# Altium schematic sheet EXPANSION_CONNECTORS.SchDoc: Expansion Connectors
size A3; Date: Not used; ApprovedBy: Not used; CheckedBy: Not used; Author: Not used; CompanyName: STMicroelectronics; DrawnBy: Not used; Engineer: Not used; Organization: Not used; Address1: Not used; Address2: Not used; Address3: Not used; Address4: Not used; DocumentNumber: Not used; Revision: Not used; SheetNumber: 13; SheetTotal: 16
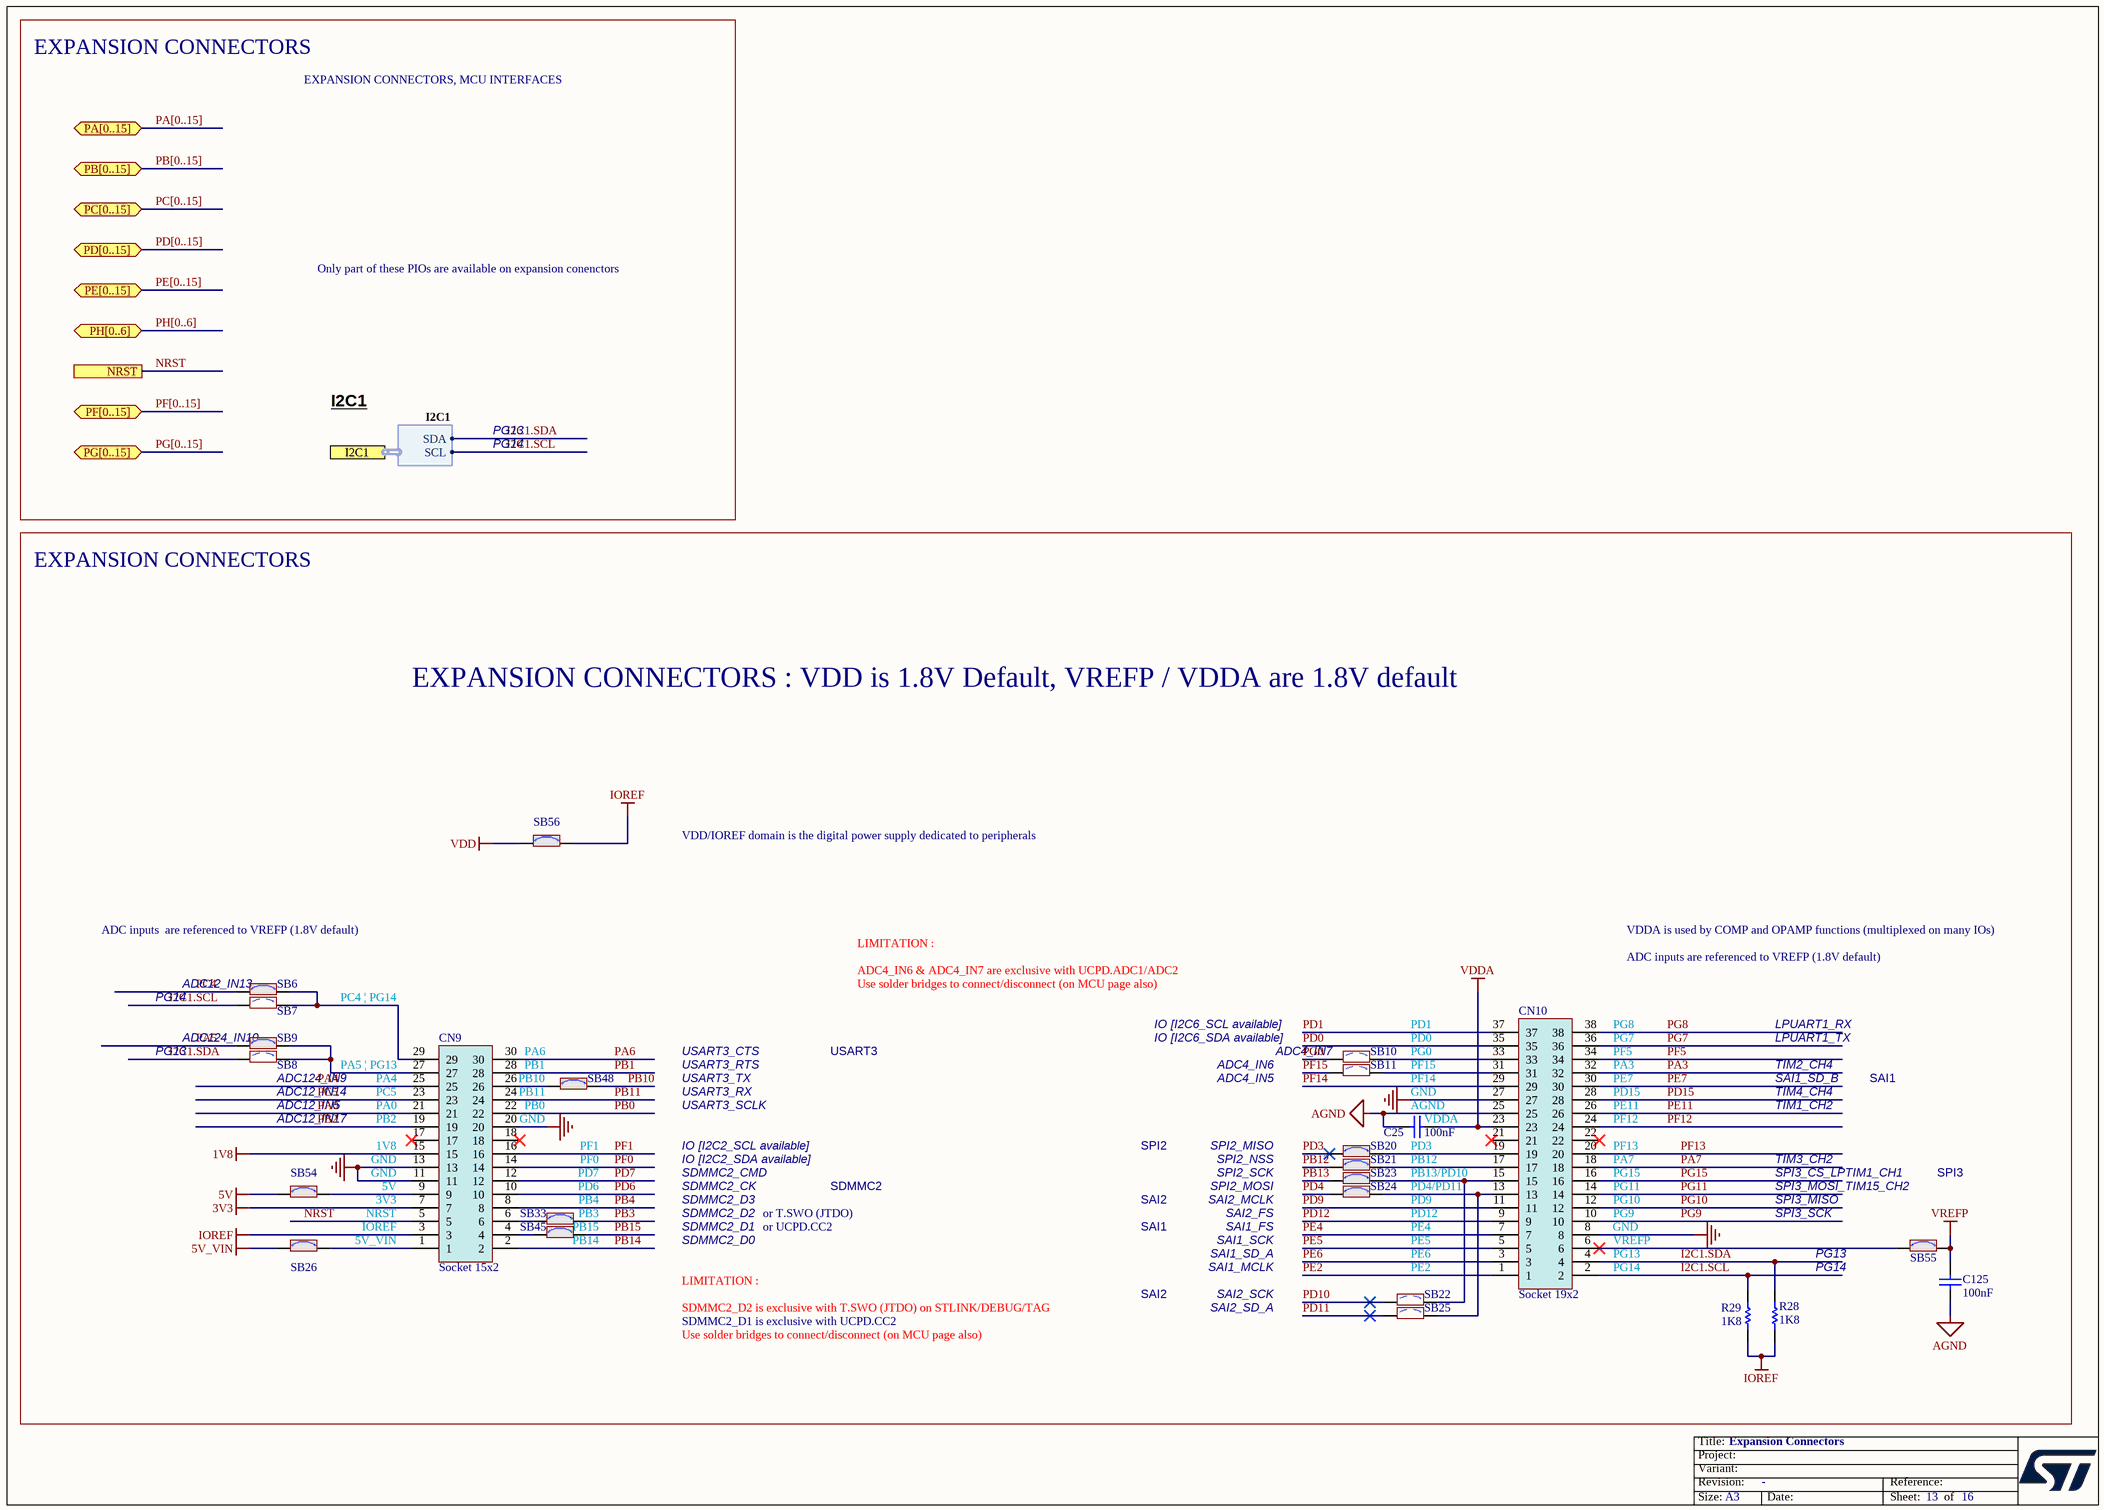
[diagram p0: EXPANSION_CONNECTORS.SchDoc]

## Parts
C25  value 100nF  [C0603]  (hidden comment: Capacitor)
C125  value 100nF  [C0603]  (hidden comment: Capacitor)
CN9  Socket 15x2  [CON_SAMTEC_SSW-115-21-F-D]
CN10  Socket 19x2  [CON_SAMTEC_SSW-119-21-F-D]
R28  value 1K8  [R0402]  (hidden comment: Resistor)
R29  value 1K8  [R0402]  (hidden comment: Resistor)
SB6  SB_ON  [SOLDER-BRIDGE_R0402-0R]  (value not drawn)
SB7  SB_OFF  [SOLDER-BRIDGE_R0402-0R]  (value not drawn)
SB8  SB_OFF  [SOLDER-BRIDGE_R0402-0R]  (value not drawn)
SB9  SB_ON  [SOLDER-BRIDGE_R0402-0R]  (value not drawn)
SB10  SB_OFF  [SOLDER-BRIDGE_R0402-0R]  (value not drawn)
SB11  SB_OFF  [SOLDER-BRIDGE_R0402-0R]  (value not drawn)
SB20  SB_ON  [SOLDER-BRIDGE_R0402-0R]  (value not drawn)
SB21  SB_ON  [SOLDER-BRIDGE_R0402-0R]  (value not drawn)
SB22  SB_OFF  [SOLDER-BRIDGE_R0402-0R]  (value not drawn)
SB23  SB_ON  [SOLDER-BRIDGE_R0402-0R]  (value not drawn)
SB24  SB_ON  [SOLDER-BRIDGE_R0402-0R]  (value not drawn)
SB25  SB_OFF  [SOLDER-BRIDGE_R0402-0R]  (value not drawn)
SB26  SB_ON  [SOLDER-BRIDGE_R0402-0R]  (value not drawn)
SB33  SB_ON  [SOLDER-BRIDGE_R0402-0R]  (value not drawn)
SB45  SB_ON  [SOLDER-BRIDGE_R0402-0R]  (value not drawn)
SB48  SB_ON  [SOLDER-BRIDGE_R0402-0R]  (value not drawn)
SB54  SB_ON  [SOLDER-BRIDGE_R0402-0R]  (value not drawn)
SB55  SB_ON  [SOLDER-BRIDGE_R0402-0R]  (value not drawn)
SB56  SB_ON  [SOLDER-BRIDGE_R0402-0R]  (value not drawn)

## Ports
I2C1 (harness I2C1), NRST, PA[0..15] (bidir), PB[0..15] (bidir), PC[0..15] (bidir), PD[0..15] (bidir), PE[0..15] (bidir), PF[0..15] (bidir), PG[0..15] (bidir), PH[0..6] (bidir)

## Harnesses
I2C1: SDA, SCL

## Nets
1V8: CN9.15
3V3: CN9.7
5V: SB54.1
5V_VIN: SB26.1
AGND: C25.1 C125.1 CN10.25
GND: CN9.11 CN9.13 CN9.20 CN10.8 CN10.27
IOREF: CN9.3 R28.2 R29.2 SB56.2
VDD: SB56.1
VDDA: C25.2 CN10.23
VREFP: C125.2 SB55.2
I2C1.SCL: CN10.2 R29.1 SB7.1 ; port I2C1.SCL
I2C1.SDA: CN10.4 R28.1 SB8.1 ; port I2C1.SDA
NRST: CN9.5 ; port NRST
PA0: CN9.21
PA3: CN10.32
PA4: CN9.25
PA5: SB9.1
PA6: CN9.30
PA7: CN10.18
PB0: CN9.22
PB1: CN9.28
PB2: CN9.19
PB3: SB33.2
PB4: CN9.8
PB10: SB48.2
PB11: CN9.24
PB12: SB21.1
PB13: SB23.1
PB14: CN9.2
PB15: SB45.2
PC4: SB6.1
PC5: CN9.23
PD0: CN10.35
PD1: CN10.37
PD3: SB20.1
PD4: SB24.1
PD6: CN9.10
PD7: CN9.12
PD9: CN10.11
PD10: SB22.1
PD11: SB25.1
PD12: CN10.9
PD15: CN10.28
PE2: CN10.1
PE4: CN10.7
PE5: CN10.5
PE6: CN10.3
PE7: CN10.30
PE11: CN10.26
PF0: CN9.14
PF1: CN9.16
PF5: CN10.34
PF12: CN10.24
PF13: CN10.20
PF14: CN10.29
PF15: SB11.1
PG0: SB10.1
PG7: CN10.36
PG8: CN10.38
PG9: CN10.10
PG10: CN10.12
PG11: CN10.14
PG15: CN10.16
NetCN9_1: CN9.1 SB26.2
NetCN9_4: CN9.4 SB45.1
NetCN9_6: CN9.6 SB33.1
NetCN9_9: CN9.9 SB54.2
NetCN9_26: CN9.26 SB48.1
NetCN9_27: CN9.27 SB8.2 SB9.2
NetCN9_29: CN9.29 SB6.2 SB7.2
NetCN10_6: CN10.6 SB55.1
NetCN10_13: CN10.13 SB24.2 SB25.2
NetCN10_15: CN10.15 SB22.2 SB23.2
NetCN10_17: CN10.17 SB21.2
NetCN10_19: CN10.19 SB20.2
NetCN10_31: CN10.31 SB11.2
NetCN10_33: CN10.33 SB10.2

Not connected (* = marked no-connect by the designer): CN9 17* 18*; CN10 21* 22*

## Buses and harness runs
bus PA[0..15] = port PA[0..15]
bus PB[0..15] = port PB[0..15]
bus PC[0..15] = port PC[0..15]
bus PD[0..15] = port PD[0..15]
bus PE[0..15] = port PE[0..15]
bus PF[0..15] = port PF[0..15]
bus PG[0..15] = port PG[0..15]
bus PH[0..6] = port PH[0..6]

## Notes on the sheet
- EXPANSION CONNECTORS
- EXPANSION CONNECTORS, MCU INTERFACES
- Only part of these PIOs are available on expansion conenctors
- I2C1
- PG13
- PG14
- EXPANSION CONNECTORS : VDD is 1.8V Default, VREFP / VDDA are 1.8V default
- VDD/IOREF domain is the digital power supply dedicated to peripherals
- ADC inputs  are referenced to VREFP (1.8V default)
- ADC12_IN13
- ADC4_IN6 & ADC4_IN7 are exclusive with UCPD.ADC1/ADC2
- Use solder bridges to connect/disconnect (on MCU page also)
- LIMITATION :
- ADC inputs are referenced to VREFP (1.8V default)
- VDDA is used by COMP and OPAMP functions (multiplexed on many IOs)
- ADC124_IN10
- PC4 ¦ PG14
- PA6
- USART3_CTS
- USART3
- IO [I2C6_SDA available]
- IO [I2C6_SCL available]
- ADC4_IN7
- PG0
- PD0
- PD1
- (near CN10) PF5
- (near CN10) PG7
- (near CN10) PG8
- LPUART1_TX
- LPUART1_RX
- ADC12_IN17
- ADC12_IN5
- ADC12_IN14
- (near SB8) ADC124_IN9
- (near CN9) PB2
- (near CN9) PA0
- (near CN9) PC5
- (near CN9) PA4
- PA5 ¦ PG13
- (near SB48) PB0
- (near SB48) PB11
- (near SB48) PB10
- (near SB48) PB1
- GND
- USART3_TX
- USART3_RX
- USART3_SCLK
- USART3_RTS
- ADC4_IN5
- ADC4_IN6
- PF14
- PF15
- (near C25) AGND
- (near C25) VDDA
- (near CN10) PF12
- (near CN10) PE11
- (near CN10) PD15
- (near CN10) PE7
- (near CN10) PA3
- TIM1_CH2
- TIM4_CH4
- TIM2_CH4
- SAI1_SD_B
- SAI1
- (near CN9) 5V
- (near CN9) GND
- (near CN9) 1V8
- PD6
- PD7
- PF0
- PF1
- SDMMC2_CK
- SDMMC2_CMD
- IO [I2C2_SDA available]
- IO [I2C2_SCL available]
- SDMMC2
- SPI2
- SPI2_MISO
- SPI2_NSS
- SPI2_MOSI
- SPI2_SCK
- PD4/PD11
- PB13/PD10
- PB12
- (near C25) PD3
- (near CN10) PF13
- (near CN10) PA7
- (near CN10) PG15
- (near CN10) PG11
- TIM3_CH2
- SPI3_CS_LPTIM1_CH1
- SPI3_MOSI_TIM15_CH2
- SPI3
- IOREF
- NRST
- 3V3
- 5V_VIN
- (near SB33) PB4
- PB3
- (near SB45) PB14
- PB15
- SDMMC2_D0
- SDMMC2_D1
- SDMMC2_D2
- SDMMC2_D3
- or T.SWO (JTDO)
- or UCPD.CC2
- SAI2
- SAI1_SD_A
- SAI1_SCK
- SAI1_FS
- SAI2_FS
- SAI2_MCLK
- PE6
- PE5
- PE4
- PD12
- PD9
- (near CN10) VREFP
- (near CN10) PG10
- (near CN10) PG9
- (near CN10) PG13
- (near CN10) GND
- SPI3_SCK
- SPI3_MISO
- SDMMC2_D2 is exclusive with T.SWO (JTDO) on STLINK/DEBUG/TAG
- SDMMC2_D1 is exclusive with UCPD.CC2
- SAI1_MCLK
- SAI2_SD_A
- SAI2_SCK
- PE2
- (near CN10) PG14

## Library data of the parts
C25 C125 = MCD-00211: Capacitor, MLCC, 100nF, 16V, X7R, +/-10%, 0603, T=0.8mm; Manufacturer_Part_Number: CC0603KRX7R7BB104; Manufacturer: YAGEO; Part_Preference: Recommended; Order_Code_RS: 669-8763; Component_Country_Of_Origin: China
CN9 = MCD-02943: Socket, 15x2, 2.54mm, VR, TH, T=8.51mm/2.64mm; Part_Type: Connector; Part_Preference: Recommended; Manufacturer: SAMTEC; Manufacturer_Part_Number: SSW-115-21-F-D; Partial_Alternate_Internal_Part_Number: MCD-02945; ShowFields: YES; ID: 5059
CN10 = MCD-02944: Socket, 19x2, 2.54mm, VR, TH, T=8.51mm/2.64mm; Part_Type: Connector; Part_Preference: Recommended; Manufacturer: SAMTEC; Manufacturer_Part_Number: SSW-119-21-F-D; Partial_Alternate_Internal_Part_Number: MCD-02946; ShowFields: YES; ID: 5060
R28 R29 = MCD-00409: Resistor, 1K8, 0402, +/-1%, 1/16W; Manufacturer_Part_Number: RC0402FR-071K8L; Manufacturer: YAGEO; Part_Preference: Recommended; Component_Country_Of_Origin: China
SB6 SB9 SB20 SB21 SB23 SB24 SB26 SB33 SB45 SB48 SB54-SB56 = MCD-01618: Solder Bridge 0402 ON; Part_Type: Misc; Manufacturer_Part_Number: RC0402JR-070RL; Manufacturer: YAGEO; Part_Preference: Recommended; Order_Code_RS: 618-5804; Component_Country_Of_Origin: China
SB7 SB8 = MCD-02162: Solder Bridge 0402 OFF; Part_Type: Misc; Manufacturer_Part_Number: RC0402JR-070RL; Manufacturer: YAGEO; Part_Preference: Recommended; Order_Code_RS: 618-5804
SB10 SB11 SB22 SB25 = MCD-02162: Solder Bridge 0402 OFF; Part_Type: Misc; Manufacturer_Part_Number: RC0402JR-070RL; Manufacturer: YAGEO; Part_Preference: Recommended; Order_Code_RS: 618-5804; Component_Country_Of_Origin: China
